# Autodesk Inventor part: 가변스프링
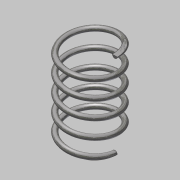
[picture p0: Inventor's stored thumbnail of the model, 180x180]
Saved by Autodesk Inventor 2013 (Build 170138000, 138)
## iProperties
Created: 2019-05
Part Number: 가변스프링
Material: 스테인리스강
Document SubType Name: Modeling
Designer: Administrator
Density: 8.08 g/cm^3
Mass: 7.87899 g
Surface Area: 19.733 cm^2
Volume: 0.975122 cm^3
Author: Administrator
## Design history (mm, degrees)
sketch "스케치1"
  geometry: L1 (0, 34)-(10, 34); L2 (10, 34)-(10, 0); L3 (10, 0)-(0, 0); L4 (0, 0)-(0, 34); C1 r 1 at (10, 0); 1 further point
  constraints: 8 end point, 2 coincident, 2 parallel, 1 centre point, 1 horizontal, 1 perpendicular
  dimensions: "d0" = 2 diameter of C1; "d2" = 34 distance between parallel lines of L3 L1 (derived); "d3" = 20 diameter of L2 L4
feature "코일1" sketch "스케치1" pitch "d4" = 10; turns "d6" = 5; dims "d5" = 34 (= d2), "d7" = 0, angle "d8" = 90 deg, angle "d9" = 90 deg, "d10" = 0, "d11" = 0
sketch "스케치2"
  geometry: L1 (34, 12.5)-(0, 12.5); L2 (0, 12.5)-(0, -12.5); L3 (0, -12.5)-(34, -12.5); L4 (34, -12.5)-(34, 12.5); 2 further points
  constraints: 8 end point, 2 parallel, 1 coincident, 1 horizontal, 1 midpoint, 1 perpendicular
  dimensions: "d12" = 34 distance between parallel lines of L2 L4 (derived); "d14" = 25 distance between parallel lines of L1 L3
extrude "돌출1" sketch "스케치2" stored distance "d15" = 30; taper "d16" = 0 deg
node "솔리드1"
